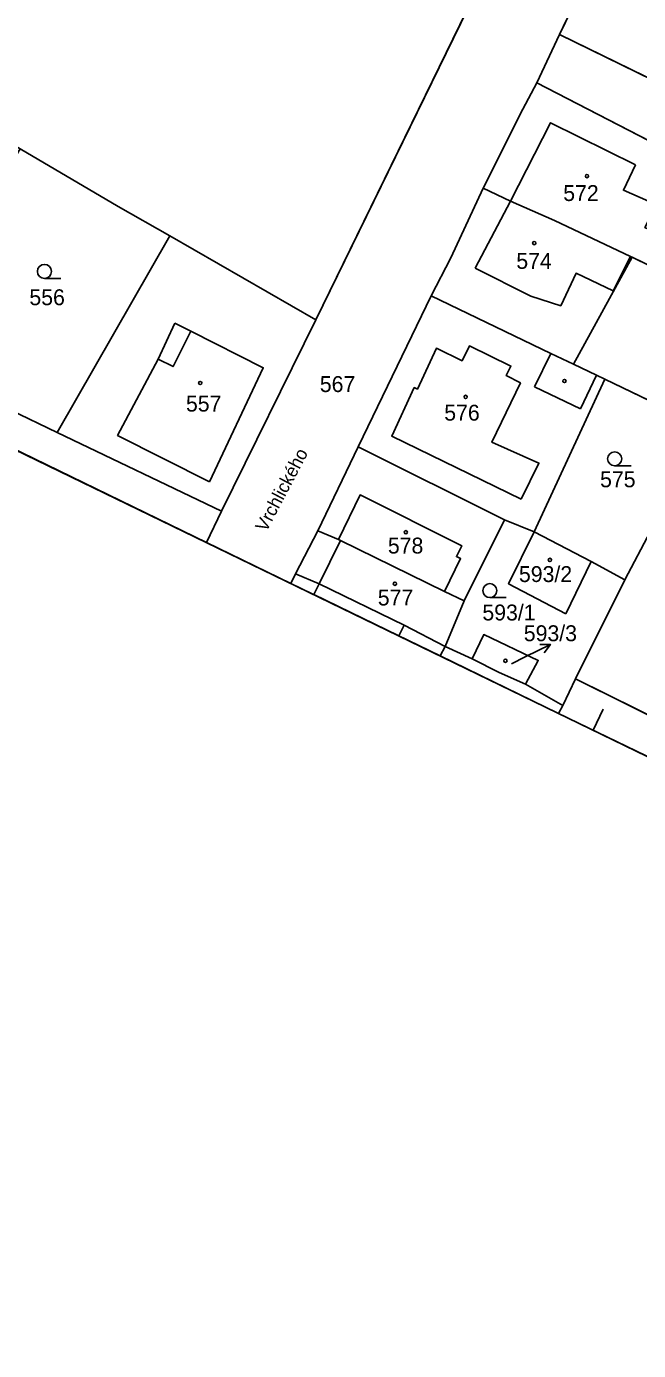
# Model space of a CAD drawing. Extents: x -762314 to -761449, y -993181 to -992589.
# Drawn here: x -762185.4 to -762119.9, y -992972.2 to -992830.6 of the extents above; entities that cross this region are included whole.
import ezdxf

# ---------------------------------------------------------------- set-up
doc = ezdxf.new("R2010")
doc.units = 0
for name, color, linetype in [('Formáty', 7, 'Continuous'), ('Hranice - vnitř_ kresba', 7, 'Continuous'), ('Hranice parcel', 7, 'Continuous'), ('Názvy', 7, 'Continuous'), ('Obvody jako plochy', 7, 'Continuous'), ('Parcelní čísla', 7, 'Continuous'), ('Prvky pro prodl_ par_ č_', 7, 'Continuous'), ('Značky kultur', 7, 'Continuous'), ('Značky na budově ne v SPI', 7, 'Continuous'), ('Značky na budově v SPI', 7, 'Continuous')]:
    doc.layers.add(name, color=color, linetype=linetype)

msp = doc.modelspace()

# ---------------------------------------------------------------- linework, layer by layer
at = {"layer": 'Formáty'}
msp.add_line((-762124.78, -992905.84), (-762123.69, -992903.59), dxfattribs=at)
msp.add_lwpolyline([(-761558.02, -993180.94), (-762313.7, -992814.14), (-762204.47, -992589.1), (-761448.79, -992955.9)], close=True, dxfattribs=at)
msp.add_lwpolyline([(-761558.02, -993180.94), (-762313.7, -992814.14), (-762204.47, -992589.1), (-761448.79, -992955.9)], close=True, dxfattribs=at)
at = {"layer": 'Hranice - vnitř_ kresba'}
for p, q in [((-762129.34, -992840.86), (-762133.6, -992849.26)), ((-762120.23, -992845.37), (-762129.34, -992840.86)), ((-762121.53, -992848.08), (-762120.23, -992845.37)), ((-762117.96, -992849.65), (-762121.53, -992848.08)), ((-762133.6, -992849.26), (-762137.38, -992856.42)), ((-762120.79, -992855.16), (-762122.64, -992858.83)), ((-762137.38, -992856.42), (-762131.43, -992859.42)), ((-762128.24, -992860.44), (-762126.6, -992856.96)), ((-762126.6, -992856.96), (-762122.64, -992858.83)), ((-762131.43, -992859.42), (-762128.24, -992860.44)), ((-762169.51, -992862.3), (-762171.31, -992866.14)), ((-762167.8, -992863.16), (-762169.51, -992862.3)), ((-762167.8, -992863.16), (-762169.71, -992866.94)), ((-762160.06, -992867.07), (-762167.8, -992863.16)), ((-762143.57, -992869.35), (-762141.54, -992864.98)), ((-762141.54, -992864.98), (-762138.79, -992866.32)), ((-762138.79, -992866.32), (-762138.01, -992864.73)), ((-762138.01, -992864.73), (-762133.57, -992866.89)), ((-762171.31, -992866.14), (-762175.65, -992874.32)), ((-762169.71, -992866.94), (-762171.31, -992866.14)), ((-762129.31, -992865.53), (-762131.03, -992869.1)), ((-762165.83, -992879.28), (-762160.06, -992867.07)), ((-762133.57, -992866.89), (-762134.08, -992867.89)), ((-762134.08, -992867.89), (-762132.55, -992868.7)), ((-762126.14, -992871.45), (-762124.42, -992867.88)), ((-762146.32, -992874.39), (-762143.91, -992869.2)), ((-762143.91, -992869.2), (-762143.57, -992869.35)), ((-762132.55, -992868.7), (-762135.6, -992875.04)), ((-762131.03, -992869.1), (-762126.14, -992871.45)), ((-762175.65, -992874.32), (-762165.83, -992879.28)), ((-762132.48, -992881.14), (-762146.32, -992874.39)), ((-762135.6, -992875.04), (-762130.58, -992877.27)), ((-762130.58, -992877.27), (-762132.48, -992881.14)), ((-762152.03, -992885.44), (-762149.71, -992880.67)), ((-762149.71, -992880.67), (-762138.83, -992886.12)), ((-762151.81, -992885.54), (-762154.08, -992890.18)), ((-762138.83, -992886.12), (-762139.4, -992887.27)), ((-762138.96, -992887.49), (-762140.69, -992891.01)), ((-762139.4, -992887.27), (-762138.96, -992887.49)), ((-762154.08, -992890.18), (-762154.66, -992891.34)), ((-762145.57, -992895.75), (-762144.98, -992894.62))]:
    msp.add_line(p, q, dxfattribs=at)
at = {"layer": 'Hranice parcel'}
for p, q in [((-762120.7, -992815.37), (-762128.36, -992831.43)), ((-762154.43, -992861.93), (-762135.84, -992823.83)), ((-762128.36, -992831.43), (-762130.78, -992836.6)), ((-762099.51, -992845.52), (-762128.36, -992831.43)), ((-762130.78, -992836.6), (-762132.31, -992839.39)), ((-762130.78, -992836.6), (-762113.12, -992845.71)), ((-762132.31, -992839.39), (-762136.55, -992847.87)), ((-762186.08, -992843.63), (-762175.57, -992849.81)), ((-762136.55, -992847.87), (-762139.98, -992855.32)), ((-762136.55, -992847.87), (-762133.6, -992849.26)), ((-762133.6, -992849.26), (-762128.92, -992851.32)), ((-762175.57, -992849.81), (-762170.05, -992852.97)), ((-762128.92, -992851.32), (-762120.79, -992855.16)), ((-762182.1, -992873.99), (-762170.05, -992852.97)), ((-762170.05, -992852.97), (-762154.43, -992861.93)), ((-762139.98, -992855.32), (-762142.11, -992859.37)), ((-762126.87, -992866.7), (-762120.61, -992855.25)), ((-762120.79, -992855.16), (-762120.61, -992855.25)), ((-762120.61, -992855.25), (-762112.88, -992859.02)), ((-762142.11, -992859.37), (-762149.92, -992875.52)), ((-762142.11, -992859.37), (-762129.31, -992865.53)), ((-762154.43, -992861.93), (-762164.52, -992882.43)), ((-762129.31, -992865.53), (-762126.87, -992866.7)), ((-762126.87, -992866.7), (-762124.42, -992867.88)), ((-762124.42, -992867.88), (-762123.52, -992868.31)), ((-762131.09, -992884.64), (-762123.52, -992868.31)), ((-762123.52, -992868.31), (-762113.3, -992873.23)), ((-762187.14, -992871.59), (-762182.1, -992873.99)), ((-762164.52, -992882.43), (-762182.1, -992873.99)), ((-762154.22, -992884.53), (-762149.92, -992875.52)), ((-762149.92, -992875.52), (-762134.26, -992883.34)), ((-762166.14, -992885.76), (-762164.52, -992882.43)), ((-762134.26, -992883.34), (-762138.58, -992892.02)), ((-762134.26, -992883.34), (-762131.09, -992884.64)), ((-762154.22, -992884.53), (-762156.62, -992889.13)), ((-762152.03, -992885.44), (-762154.22, -992884.53)), ((-762131.09, -992884.64), (-762133.82, -992890.18)), ((-762131.09, -992884.64), (-762125, -992887.79)), ((-762121.4, -992889.77), (-762118.64, -992884.57)), ((-762151.81, -992885.54), (-762152.03, -992885.44)), ((-762140.69, -992891.01), (-762151.81, -992885.54)), ((-762127.7, -992893.42), (-762125, -992887.79)), ((-762125, -992887.79), (-762121.4, -992889.77)), ((-762156.62, -992889.13), (-762157.11, -992890.15)), ((-762156.62, -992889.13), (-762154.08, -992890.18)), ((-762154.08, -992890.18), (-762144.98, -992894.62)), ((-762133.82, -992890.18), (-762127.7, -992893.42)), ((-762121.4, -992889.77), (-762126.66, -992900.34)), ((-762138.58, -992892.02), (-762140.69, -992891.01)), ((-762140.59, -992896.9), (-762138.58, -992892.02)), ((-762144.98, -992894.62), (-762140.59, -992896.9)), ((-762137.73, -992898.21), (-762136.47, -992895.63)), ((-762136.47, -992895.63), (-762130.65, -992898.38)), ((-762140.59, -992896.9), (-762141.13, -992897.91)), ((-762137.73, -992898.21), (-762140.59, -992896.9)), ((-762137.73, -992898.21), (-762134.82, -992899.67)), ((-762130.65, -992898.38), (-762132.01, -992900.94)), ((-762132.01, -992900.94), (-762134.82, -992899.67)), ((-762126.66, -992900.34), (-762128, -992903.2)), ((-762115.47, -992905.91), (-762126.66, -992900.34)), ((-762128, -992903.2), (-762132.01, -992900.94)), ((-762128.47, -992904.05), (-762128, -992903.2))]:
    msp.add_line(p, q, dxfattribs=at)
at = {"layer": 'Obvody jako plochy'}
for p, q in [((-762129.34, -992840.86), (-762133.6, -992849.26)), ((-762120.23, -992845.37), (-762129.34, -992840.86)), ((-762121.53, -992848.08), (-762120.23, -992845.37)), ((-762117.96, -992849.65), (-762121.53, -992848.08)), ((-762133.6, -992849.26), (-762137.38, -992856.42)), ((-762133.6, -992849.26), (-762128.92, -992851.32)), ((-762133.6, -992849.26), (-762128.92, -992851.32)), ((-762128.92, -992851.32), (-762120.79, -992855.16)), ((-762128.92, -992851.32), (-762120.79, -992855.16)), ((-762120.79, -992855.16), (-762122.64, -992858.83)), ((-762120.79, -992855.16), (-762120.61, -992855.25)), ((-762120.61, -992855.25), (-762112.88, -992859.02)), ((-762137.38, -992856.42), (-762131.43, -992859.42)), ((-762128.24, -992860.44), (-762126.6, -992856.96)), ((-762126.6, -992856.96), (-762122.64, -992858.83)), ((-762131.43, -992859.42), (-762128.24, -992860.44)), ((-762167.8, -992863.16), (-762169.71, -992866.94)), ((-762160.06, -992867.07), (-762167.8, -992863.16)), ((-762143.57, -992869.35), (-762141.54, -992864.98)), ((-762141.54, -992864.98), (-762138.79, -992866.32)), ((-762138.79, -992866.32), (-762138.01, -992864.73)), ((-762138.01, -992864.73), (-762133.57, -992866.89)), ((-762171.31, -992866.14), (-762175.65, -992874.32)), ((-762169.71, -992866.94), (-762171.31, -992866.14)), ((-762165.83, -992879.28), (-762160.06, -992867.07)), ((-762133.57, -992866.89), (-762134.08, -992867.89)), ((-762134.08, -992867.89), (-762132.55, -992868.7)), ((-762146.32, -992874.39), (-762143.91, -992869.2)), ((-762143.91, -992869.2), (-762143.57, -992869.35)), ((-762132.55, -992868.7), (-762135.6, -992875.04)), ((-762188.54, -992874.89), (-762166.14, -992885.76)), ((-762175.65, -992874.32), (-762165.83, -992879.28)), ((-762132.48, -992881.14), (-762146.32, -992874.39)), ((-762135.6, -992875.04), (-762130.58, -992877.27)), ((-762130.58, -992877.27), (-762132.48, -992881.14)), ((-762152.03, -992885.44), (-762149.71, -992880.67)), ((-762149.71, -992880.67), (-762138.83, -992886.12)), ((-762131.09, -992884.64), (-762133.82, -992890.18)), ((-762131.09, -992884.64), (-762125, -992887.79)), ((-762166.14, -992885.76), (-762157.11, -992890.15)), ((-762151.81, -992885.54), (-762154.08, -992890.18)), ((-762151.81, -992885.54), (-762152.03, -992885.44)), ((-762140.69, -992891.01), (-762151.81, -992885.54)), ((-762140.69, -992891.01), (-762151.81, -992885.54)), ((-762138.83, -992886.12), (-762139.4, -992887.27)), ((-762138.96, -992887.49), (-762140.69, -992891.01)), ((-762139.4, -992887.27), (-762138.96, -992887.49)), ((-762127.7, -992893.42), (-762125, -992887.79)), ((-762157.11, -992890.15), (-762141.13, -992897.91)), ((-762154.08, -992890.18), (-762154.66, -992891.34)), ((-762154.08, -992890.18), (-762144.98, -992894.62)), ((-762154.08, -992890.18), (-762144.98, -992894.62)), ((-762133.82, -992890.18), (-762127.7, -992893.42)), ((-762154.66, -992891.34), (-762145.57, -992895.75)), ((-762138.58, -992892.02), (-762140.69, -992891.01)), ((-762140.59, -992896.9), (-762138.58, -992892.02)), ((-762145.57, -992895.75), (-762144.98, -992894.62)), ((-762144.98, -992894.62), (-762140.59, -992896.9)), ((-762137.73, -992898.21), (-762136.47, -992895.63)), ((-762136.47, -992895.63), (-762130.65, -992898.38)), ((-762141.13, -992897.91), (-762128.47, -992904.05)), ((-762137.73, -992898.21), (-762134.82, -992899.67)), ((-762130.65, -992898.38), (-762132.01, -992900.94)), ((-762132.01, -992900.94), (-762134.82, -992899.67)), ((-762128.47, -992904.05), (-762117.12, -992909.56))]:
    msp.add_line(p, q, dxfattribs=at)
for points in [[(-762161.71, -992773.83), (-762162.49, -992775.36), (-762164.2, -992774.71), (-762168.6, -992783.13), (-762185.7, -992816.46), (-762191.12, -992813.77), (-762192.68, -992817.24), (-762193.39, -992818.32), (-762197.3, -992825.69), (-762201.64, -992834.59), (-762186.08, -992843.63), (-762175.57, -992849.81), (-762170.05, -992852.97), (-762154.43, -992861.93), (-762135.84, -992823.83), (-762143.56, -992819.92), (-762152.62, -992815.33), (-762149.77, -992809.58), (-762142.87, -992799.64), (-762141.57, -992797.76), (-762136.41, -992790.61), (-762152.77, -992779.05), (-762155.47, -992777.14), (-762160.33, -992774.56)], [(-762120.7, -992815.37), (-762128.36, -992831.43), (-762099.51, -992845.52), (-762088.79, -992823.09), (-762099.21, -992815.31), (-762106.52, -992823.27), (-762107.94, -992825.87), (-762109.78, -992824.94), (-762111.48, -992828.29), (-762120.99, -992823.77), (-762116.58, -992814.62), (-762119.3, -992813.87)], [(-762128.36, -992831.43), (-762130.78, -992836.6), (-762113.12, -992845.71), (-762111.23, -992855.75), (-762112.88, -992859.02), (-762107.32, -992861.46), (-762103.29, -992853.57), (-762101.93, -992850.34), (-762099.51, -992845.52)], [(-762130.78, -992836.6), (-762132.31, -992839.39), (-762136.55, -992847.87), (-762133.6, -992849.26), (-762128.92, -992851.32), (-762120.79, -992855.16), (-762120.61, -992855.25), (-762112.88, -992859.02), (-762111.23, -992855.75), (-762113.12, -992845.71)], [(-762120.23, -992845.37), (-762129.34, -992840.86), (-762133.6, -992849.26), (-762128.92, -992851.32), (-762120.79, -992855.16), (-762120.61, -992855.25), (-762112.88, -992859.02), (-762111.23, -992855.75), (-762119.23, -992852.07), (-762117.96, -992849.65), (-762121.53, -992848.08)], [(-762189.83, -992849.89), (-762186.08, -992843.63), (-762175.57, -992849.81), (-762170.05, -992852.97), (-762182.1, -992873.99), (-762187.14, -992871.59), (-762190, -992870.06), (-762192.48, -992868.73), (-762197.43, -992866.62), (-762196.1, -992863.62), (-762193.65, -992859.04)], [(-762128.92, -992851.32), (-762120.79, -992855.16), (-762120.61, -992855.25), (-762126.87, -992866.7), (-762129.31, -992865.53), (-762142.11, -992859.37), (-762139.98, -992855.32), (-762136.55, -992847.87), (-762133.6, -992849.26)], [(-762137.38, -992856.42), (-762131.43, -992859.42), (-762128.24, -992860.44), (-762126.6, -992856.96), (-762122.64, -992858.83), (-762120.79, -992855.16), (-762128.92, -992851.32), (-762133.6, -992849.26)], [(-762182.1, -992873.99), (-762170.05, -992852.97), (-762154.43, -992861.93), (-762164.52, -992882.43)], [(-762120.61, -992855.25), (-762112.88, -992859.02), (-762107.32, -992861.46), (-762110.83, -992868.23), (-762113.3, -992873.23), (-762123.52, -992868.31), (-762124.42, -992867.88), (-762126.87, -992866.7)], [(-762126.87, -992866.7), (-762124.42, -992867.88), (-762123.52, -992868.31), (-762131.09, -992884.64), (-762134.26, -992883.34), (-762149.92, -992875.52), (-762142.11, -992859.37), (-762129.31, -992865.53)], [(-762165.83, -992879.28), (-762160.06, -992867.07), (-762167.8, -992863.16), (-762169.71, -992866.94), (-762171.31, -992866.14), (-762175.65, -992874.32)], [(-762132.48, -992881.14), (-762146.32, -992874.39), (-762143.91, -992869.2), (-762143.57, -992869.35), (-762141.54, -992864.98), (-762138.79, -992866.32), (-762138.01, -992864.73), (-762133.57, -992866.89), (-762134.08, -992867.89), (-762132.55, -992868.7), (-762135.6, -992875.04), (-762130.58, -992877.27)], [(-762123.52, -992868.31), (-762113.3, -992873.23), (-762118.64, -992884.57), (-762121.4, -992889.77), (-762125, -992887.79), (-762131.09, -992884.64)], [(-762149.92, -992875.52), (-762134.26, -992883.34), (-762138.58, -992892.02), (-762140.69, -992891.01), (-762151.81, -992885.54), (-762152.03, -992885.44), (-762154.22, -992884.53)], [(-762151.81, -992885.54), (-762152.03, -992885.44), (-762149.71, -992880.67), (-762138.83, -992886.12), (-762139.4, -992887.27), (-762138.96, -992887.49), (-762140.69, -992891.01)], [(-762138.58, -992892.02), (-762140.69, -992891.01), (-762151.81, -992885.54), (-762152.03, -992885.44), (-762154.22, -992884.53), (-762156.62, -992889.13), (-762154.08, -992890.18), (-762144.98, -992894.62), (-762140.59, -992896.9)], [(-762127.7, -992893.42), (-762125, -992887.79), (-762131.09, -992884.64), (-762133.82, -992890.18)], [(-762114.33, -992893.02), (-762118.22, -992890.93), (-762116.64, -992888.05), (-762116.8, -992887.9), (-762115.88, -992885.98), (-762118.64, -992884.57), (-762121.4, -992889.77), (-762126.66, -992900.34), (-762115.47, -992905.91), (-762115.28, -992906), (-762112.95, -992901.51), (-762111.48, -992898.67), (-762110.53, -992899.11), (-762109.23, -992894.95), (-762113.5, -992892.64), (-762113.35, -992892.18), (-762113.83, -992891.88)], [(-762140.69, -992891.01), (-762151.81, -992885.54), (-762154.08, -992890.18), (-762144.98, -992894.62), (-762140.59, -992896.9), (-762138.58, -992892.02)], [(-762137.73, -992898.21), (-762134.82, -992899.67), (-762132.01, -992900.94), (-762130.65, -992898.38), (-762136.47, -992895.63)]]:
    msp.add_lwpolyline(points, close=True, dxfattribs=at)
for points in [[(-762157.11, -992890.15), (-762156.62, -992889.13), (-762154.22, -992884.53), (-762149.92, -992875.52), (-762142.11, -992859.37), (-762139.98, -992855.32), (-762136.55, -992847.87), (-762132.31, -992839.39), (-762130.78, -992836.6), (-762128.36, -992831.43), (-762120.7, -992815.37)], [(-762135.84, -992823.83), (-762154.43, -992861.93), (-762164.52, -992882.43), (-762166.14, -992885.76)], [(-762166.14, -992885.76), (-762164.52, -992882.43), (-762182.1, -992873.99), (-762187.14, -992871.59), (-762188.54, -992874.89)], [(-762141.13, -992897.91), (-762140.59, -992896.9), (-762144.98, -992894.62), (-762154.08, -992890.18), (-762156.62, -992889.13), (-762157.11, -992890.15)], [(-762145.57, -992895.75), (-762144.98, -992894.62), (-762154.08, -992890.18), (-762154.66, -992891.34)], [(-762128.47, -992904.05), (-762128, -992903.2), (-762132.01, -992900.94), (-762134.82, -992899.67), (-762137.73, -992898.21), (-762140.59, -992896.9), (-762141.13, -992897.91)], [(-762117.12, -992909.56), (-762115.47, -992905.91), (-762126.66, -992900.34), (-762128, -992903.2), (-762128.47, -992904.05)]]:
    msp.add_lwpolyline(points, dxfattribs=at)
at = {"layer": 'Prvky pro prodl_ par_ č_'}
for p, q in [((-762132.03, -992898.01), (-762129.34, -992896.68)), ((-762133.51, -992898.74), (-762132.03, -992898.01))]:
    msp.add_line(p, q, dxfattribs=at)
msp.add_lwpolyline([(-762130.46, -992896.67), (-762129.34, -992896.68), (-762130.02, -992897.57)], dxfattribs=at)
at = {"layer": 'Značky kultur'}
for p, q in [((-762181.72, -992857.51), (-762183.47, -992857.51)), ((-762120.72, -992877.57), (-762122.47, -992877.57)), ((-762134.07, -992891.67), (-762135.82, -992891.67))]:
    msp.add_line(p, q, dxfattribs=at)
for centre in [(-762183.47, -992856.76), (-762122.47, -992876.82), (-762135.82, -992890.92)]:
    msp.add_circle(centre, 0.75, dxfattribs=at)
at = {"layer": 'Značky na budově ne v SPI'}
msp.add_circle((-762127.84, -992868.49), 0.175, dxfattribs=at)
at = {"layer": 'Značky na budově v SPI'}
for centre in [(-762125.43, -992846.57), (-762131.07, -992853.74), (-762166.81, -992868.7), (-762138.41, -992870.19), (-762144.81, -992884.67), (-762129.4, -992887.63), (-762145.98, -992890.18), (-762134.15, -992898.43)]:
    msp.add_circle(centre, 0.175, dxfattribs=at)

# ---------------------------------------------------------------- texts
at = {"layer": 'Názvy'}
msp.add_text('Vrchlického', height=1.4, rotation=62.2125, dxfattribs=at).set_placement((-762159.74, -992884.73))
at = {"layer": 'Parcelní čísla'}
for s, height, p in [('572', 1.7, (-762127.97, -992849.23)), ('574', 1.7, (-762132.99, -992856.49)), ('556', 1.7, (-762185.08, -992860.38)), ('567', 1.7, (-762154.01, -992869.67)), ('557', 1.7, (-762168.33, -992871.76)), ('576', 1.7, (-762140.7, -992872.73)), ('575', 1.7, (-762124.03, -992879.86)), ('578', 1.7, (-762146.73, -992886.95)), ('593/2', 1.7, (-762132.71, -992890)), ('577', 1.7, (-762147.81, -992892.51)), ('593/1', 1.7, (-762136.62, -992894.11)), ('593/3', 0.1, (-762133.51, -992898.74))]:
    msp.add_text(s, height=height, dxfattribs=at).set_placement(p)
at = {"layer": 'Prvky pro prodl_ par_ č_'}
msp.add_text('593/3', height=1.7, dxfattribs=at).set_placement((-762132.19, -992896.33))

doc.saveas('drawing.dxf')
